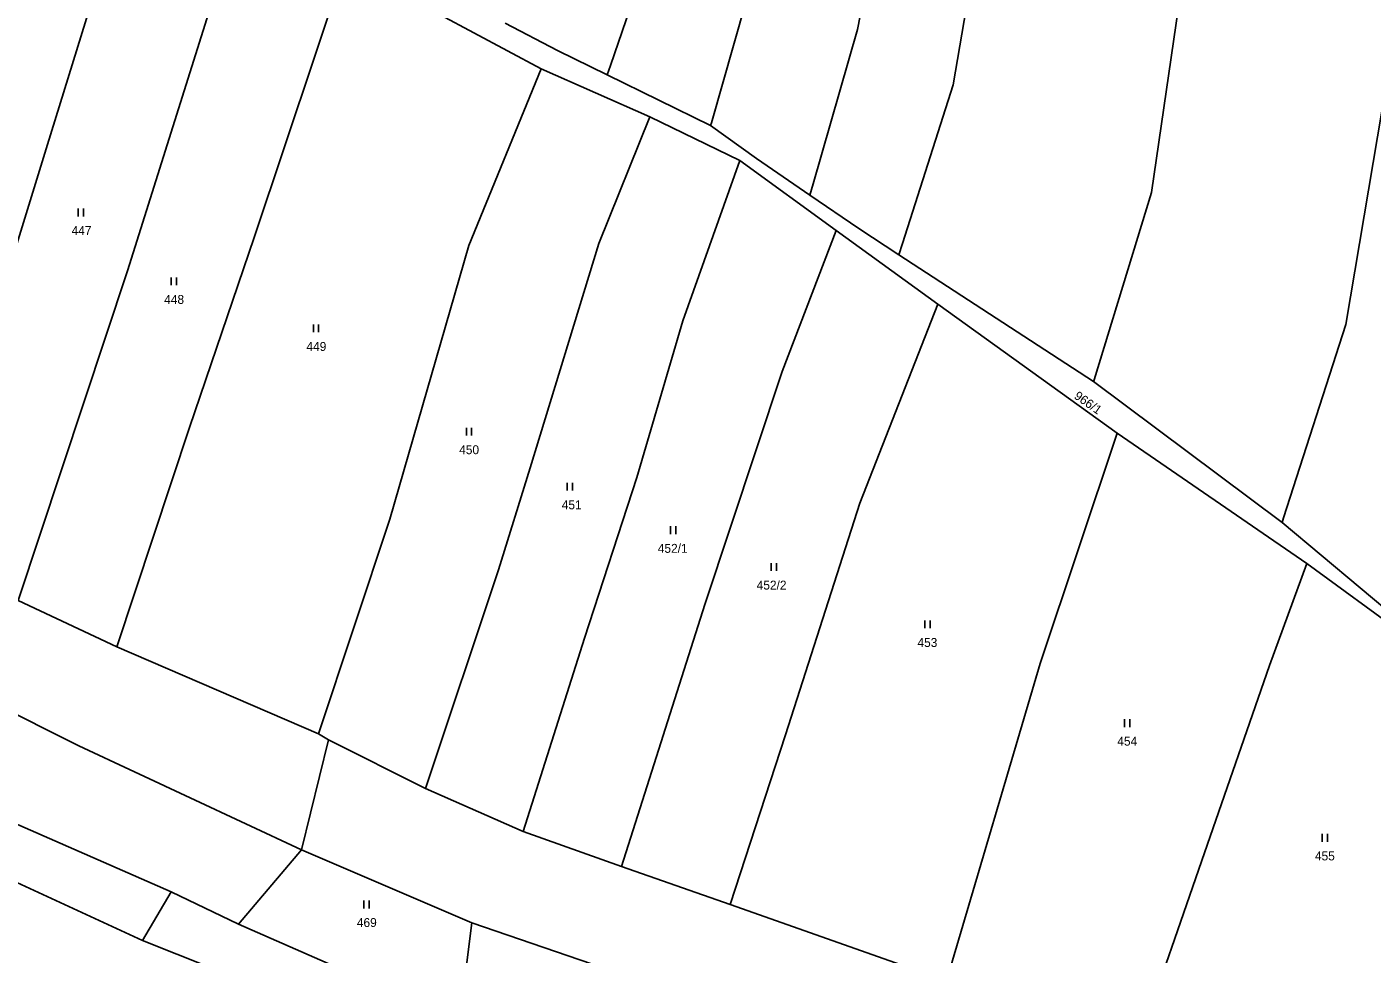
# Model space of a CAD drawing. Extents: x -7476540 to -746055, y -11317203 to -1129777.
# Drawn here: x -748441 to -748184.6, y -1130603 to -1130426.4 of the extents above; entities that cross this region are included whole.
import ezdxf

# ---------------------------------------------------------------- set-up
doc = ezdxf.new("R2010")
doc.units = 0
for name, color, linetype in [('Hranice parcel', 7, 'Continuous'), ('Parcelní čísla', 7, 'Continuous'), ('Značky kultur', 7, 'Continuous')]:
    doc.layers.add(name, color=color, linetype=linetype)

msp = doc.modelspace()

# ---------------------------------------------------------------- linework, layer by layer
at = {"layer": 'Hranice parcel'}
for p, q in [((-748380.24, -1130414.38), (-748342.98, -1130434.33)), ((-748342.98, -1130434.33), (-748322.28, -1130443.45)), ((-748310.69, -1130445.15), (-748330.38, -1130435.49)), ((-748322.28, -1130443.45), (-748305.1, -1130451.81)), ((-748305.1, -1130451.81), (-748286.73, -1130465.15)), ((-748286.73, -1130465.15), (-748267.37, -1130479.15)), ((-748237.71, -1130493.88), (-748274.78, -1130469.75)), ((-748267.37, -1130479.15), (-748233.17, -1130503.73)), ((-748201.78, -1130520.76), (-748237.71, -1130493.88)), ((-748233.17, -1130503.73), (-748197.06, -1130528.56)), ((-748442.63, -1130535.63), (-748423.83, -1130544.43)), ((-748423.83, -1130544.43), (-748385.43, -1130560.99)), ((-748383.52, -1130562.14), (-748388.62, -1130583.11)), ((-748385.43, -1130560.99), (-748383.52, -1130562.14)), ((-748383.52, -1130562.14), (-748365.02, -1130571.43)), ((-748365.02, -1130571.43), (-748346.39, -1130579.64)), ((-748346.39, -1130579.64), (-748327.67, -1130586.29)), ((-748400.65, -1130597.24), (-748388.62, -1130583.11)), ((-748388.62, -1130583.11), (-748356.21, -1130597)), ((-748327.67, -1130586.29), (-748306.94, -1130593.5)), ((-748413.5, -1130591.12), (-748418.92, -1130600.37)), ((-748413.5, -1130591.12), (-748400.65, -1130597.24)), ((-748306.94, -1130593.5), (-748265.75, -1130608.04)), ((-748357.28, -1130605.56), (-748356.21, -1130597)), ((-748356.21, -1130597), (-748301.06, -1130615.84))]:
    msp.add_line(p, q, dxfattribs=at)
for points in [[(-748130.22, -1130087.61), (-748131.13, -1130105.98), (-748132.47, -1130123.43), (-748138.48, -1130165.82), (-748139.67, -1130175.32), (-748144.94, -1130218.98), (-748149.15, -1130242.84), (-748155.25, -1130281.49), (-748166.79, -1130346.74), (-748175.48, -1130397.01), (-748180.06, -1130426.59), (-748189.62, -1130483.05), (-748201.5, -1130519.88), (-748201.78, -1130520.76)], [(-748169.91, -1130092.32), (-748177.35, -1130147.37), (-748182.55, -1130189.99), (-748186.18, -1130220.14), (-748188.49, -1130234.32), (-748193.97, -1130267.58), (-748201.44, -1130315.33), (-748212.24, -1130367.23), (-748215.27, -1130383.11), (-748220.54, -1130416.01), (-748226.63, -1130457.88), (-748237.61, -1130493.57), (-748237.71, -1130493.88)], [(-748273.39, -1130097.24), (-748281.27, -1130156.73), (-748287.31, -1130202.54), (-748290.79, -1130232.85), (-748299.54, -1130289.08), (-748301.91, -1130302.35), (-748302.4, -1130309.37), (-748305.11, -1130326.61), (-748309.55, -1130348.99), (-748320.05, -1130405.29), (-748329.77, -1130433.7), (-748330.38, -1130435.49)], [(-748230.76, -1130101.5), (-748238.92, -1130155.41), (-748244.23, -1130193.64), (-748250.06, -1130231.72), (-748257.56, -1130283.34), (-748263.19, -1130320.1), (-748266.04, -1130338.03), (-748272.57, -1130374.93), (-748282.67, -1130426.83), (-748291.12, -1130456.26), (-748291.74, -1130458.41)], [(-748211.28, -1130100.51), (-748218.94, -1130146.82), (-748219.36, -1130157.24), (-748223.16, -1130188.85), (-748229.48, -1130229.5), (-748236.23, -1130271.46), (-748240.43, -1130308.77), (-748250.12, -1130359.49), (-748258.18, -1130400.55), (-748264.43, -1130437.38), (-748274.1, -1130467.62), (-748274.78, -1130469.75)], [(-748252.59, -1130102.61), (-748256.07, -1130126.15), (-748263.51, -1130176.19), (-748266.5, -1130195.5), (-748271.15, -1130229.91), (-748277.05, -1130270.85), (-748279.2, -1130292.94), (-748282.82, -1130314.7), (-748292.75, -1130368.29), (-748301.85, -1130414.23), (-748310.54, -1130444.61), (-748310.69, -1130445.15)], [(-748462.95, -1130526.39), (-748452.24, -1130498.41), (-748444.7, -1130473.49), (-748437.34, -1130449.55), (-748416.99, -1130383.85)], [(-748442.63, -1130535.63), (-748421.81, -1130472.84), (-748398.74, -1130399.57)], [(-748423.83, -1130544.43), (-748409.99, -1130502.63), (-748397.69, -1130466.45), (-748380.24, -1130414.38)], [(-748330.38, -1130435.49), (-748339.87, -1130430.84), (-748349.86, -1130425.63)], [(-748385.43, -1130560.99), (-748371.83, -1130520.13), (-748356.78, -1130467.99), (-748342.98, -1130434.33)], [(-748365.02, -1130571.43), (-748351.1, -1130529.74), (-748345.06, -1130510.33), (-748332.01, -1130467.6), (-748322.28, -1130443.45)], [(-748291.74, -1130458.41), (-748301.96, -1130451.39), (-748310.69, -1130445.15)], [(-748346.39, -1130579.64), (-748334.71, -1130542.76), (-748324.77, -1130512.21), (-748315.97, -1130482.36), (-748305.1, -1130451.81)], [(-748274.78, -1130469.75), (-748282.46, -1130464.75), (-748291.74, -1130458.41)], [(-748327.67, -1130586.29), (-748311.77, -1130536.36), (-748297.02, -1130491.98), (-748286.73, -1130465.15)], [(-748306.94, -1130593.5), (-748296.39, -1130561.23), (-748282.24, -1130517.07), (-748267.37, -1130479.15)], [(-748265.75, -1130608.04), (-748247.9, -1130547.61), (-748233.17, -1130503.73)], [(-748526.29, -1130515.48), (-748486.84, -1130536.66), (-748470.75, -1130543.61), (-748464.43, -1130546.57), (-748431.07, -1130563.27), (-748388.62, -1130583.11)], [(-748162.54, -1130550.9), (-748179.44, -1130539.41), (-748201.78, -1130520.76)], [(-748229.57, -1130621.28), (-748216.56, -1130583.68), (-748204.16, -1130547.99), (-748197.06, -1130528.56)], [(-748197.06, -1130528.56), (-748178.46, -1130542.16), (-748161.77, -1130554.58)], [(-748516.42, -1130541.69), (-748493.99, -1130554.85), (-748454.25, -1130573.29), (-748413.5, -1130591.12)], [(-748511.31, -1130555.77), (-748507.24, -1130559.45), (-748489.41, -1130567.71), (-748456.16, -1130583.21), (-748418.92, -1130600.37)], [(-748400.65, -1130597.24), (-748378.93, -1130606.77), (-748358.56, -1130614.59)], [(-748418.92, -1130600.37), (-748345.69, -1130629.51), (-748298.06, -1130647.31)]]:
    msp.add_lwpolyline(points, dxfattribs=at)
at = {"layer": 'Značky kultur'}
for p, q in [((-748431.19, -1130462.45), (-748431.19, -1130460.95)), ((-748430.19, -1130462.45), (-748430.19, -1130460.95)), ((-748413.49, -1130475.56), (-748413.49, -1130474.06)), ((-748412.49, -1130475.56), (-748412.49, -1130474.06)), ((-748386.39, -1130484.52), (-748386.39, -1130483.02)), ((-748385.39, -1130484.52), (-748385.39, -1130483.02)), ((-748357.22, -1130504.19), (-748357.22, -1130502.69)), ((-748356.22, -1130504.19), (-748356.22, -1130502.69)), ((-748338, -1130514.68), (-748338, -1130513.18)), ((-748337, -1130514.68), (-748337, -1130513.18)), ((-748318.33, -1130522.98), (-748318.33, -1130521.48)), ((-748317.33, -1130522.98), (-748317.33, -1130521.48)), ((-748299.11, -1130529.98), (-748299.11, -1130528.48)), ((-748298.11, -1130529.98), (-748298.11, -1130528.48)), ((-748269.83, -1130540.91), (-748269.83, -1130539.41)), ((-748268.83, -1130540.91), (-748268.83, -1130539.41)), ((-748231.81, -1130559.71), (-748231.81, -1130558.21)), ((-748230.81, -1130559.71), (-748230.81, -1130558.21)), ((-748194.11, -1130581.57), (-748194.11, -1130580.07)), ((-748193.11, -1130581.57), (-748193.11, -1130580.07)), ((-748376.78, -1130594.26), (-748376.78, -1130592.76)), ((-748375.78, -1130594.26), (-748375.78, -1130592.76))]:
    msp.add_line(p, q, dxfattribs=at)

# ---------------------------------------------------------------- texts
at = {"layer": 'Parcelní čísla'}
for s, p in [('447', (-748432.47, -1130466)), ('448', (-748414.82, -1130479.11)), ('449', (-748387.71, -1130488.07)), ('450', (-748358.6, -1130507.74)), ('451', (-748339.05, -1130518.23)), ('452/1', (-748320.75, -1130526.53)), ('452/2', (-748301.9, -1130533.53)), ('453', (-748271.26, -1130544.46)), ('454', (-748233.17, -1130563.26)), ('455', (-748195.51, -1130585.12)), ('469', (-748378.1, -1130597.81))]:
    msp.add_text(s, height=1.7, dxfattribs=at).set_placement(p)
msp.add_text('966/1', height=1.7, rotation=325, dxfattribs=at).set_placement((-748241.55, -1130497))

doc.saveas('drawing.dxf')
